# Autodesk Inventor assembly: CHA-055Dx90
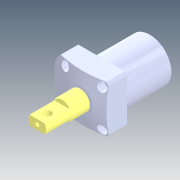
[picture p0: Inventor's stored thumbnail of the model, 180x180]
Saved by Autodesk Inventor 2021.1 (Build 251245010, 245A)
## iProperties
Created: 2018-07
Part Number: CHA-055Dx90
Description: STEP AP214
Document SubType Name: Assembly
Designer: user
Title: CHA-055Dx90.STEP
Revision Number: ÈÎºÎ
Sending System: SolidWorks 2016
Preprocessor: SwSTEP 2.0
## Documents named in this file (3)
- D:\Vault_2016\Projekty\Clamptek\Hydraulic\CHA\CHA\CHA-055\Inventor\CHA-055Dx90\CHA-055Dx90.iam
- D:\Vault_2016\Projekty\Clamptek\Hydraulic\CHA\CHA\CHA-055\Inventor\CHA-055Dx90\CHA-055±¾Ìå.ipt
- D:\Vault_2016\Projekty\Clamptek\Hydraulic\CHA\CHA\CHA-055\Inventor\CHA-055Dx90\CHA-055(Ë«±Û£©»îÈû¸Ë.ipt
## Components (2 placed, 2 different names)
1. CHA-055±¾Ìå_1
2. CHA-055(Ë«±Û£©»îÈû¸Ë_2
